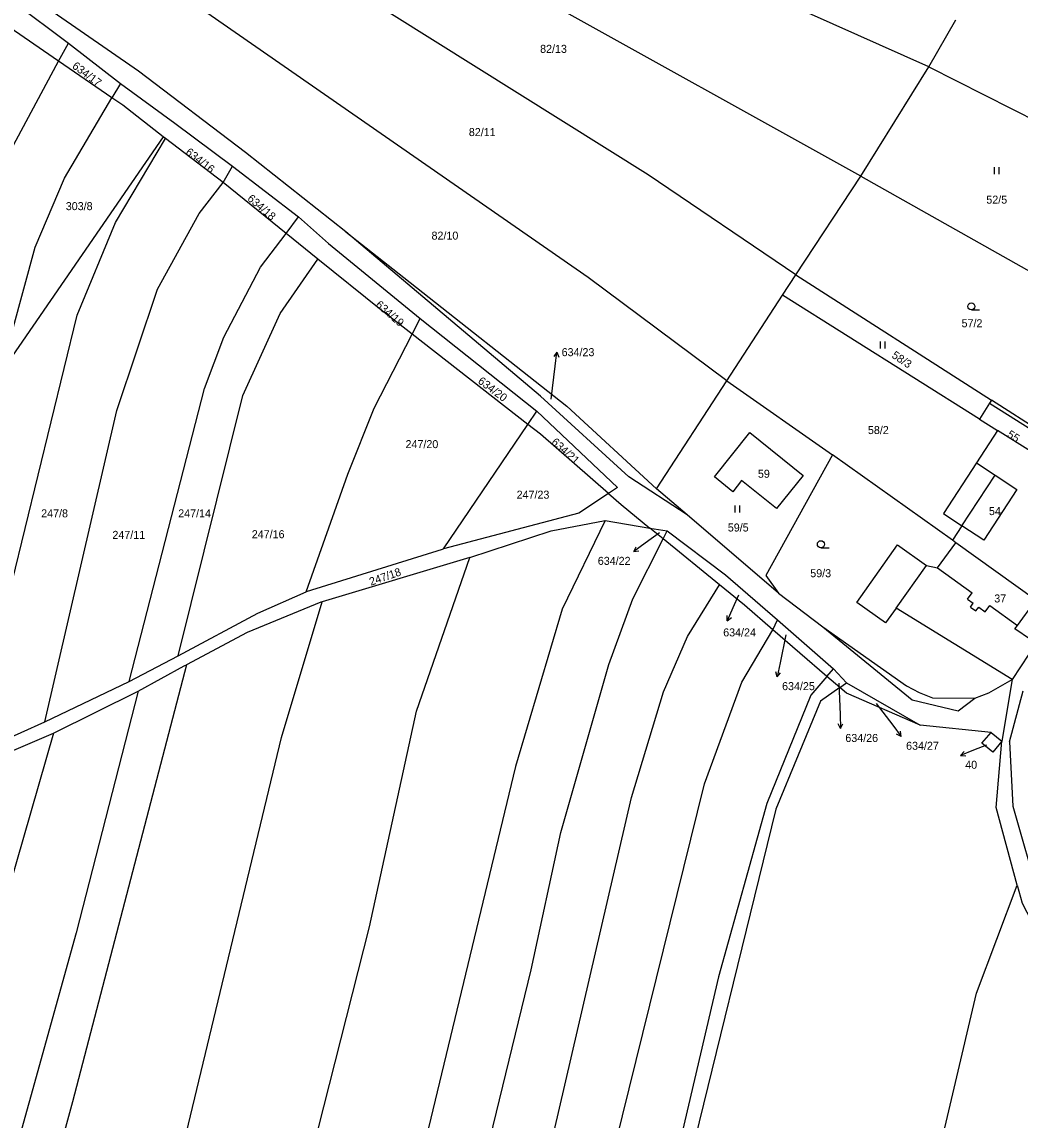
# Model space of a CAD drawing. Extents: x -744566 to -741843, y -1128407 to -1126744.
# Drawn here: x -743260.5 to -743048.6, y -1127789.3 to -1127556.1 of the extents above; entities that cross this region are included whole.
import ezdxf

# ---------------------------------------------------------------- set-up
doc = ezdxf.new("R2010")
doc.units = 0
for name, color, linetype in [('Hranice parcel', 7, 'Continuous'), ('Parcelní čísla', 7, 'Continuous'), ('Pop  PČ popisy', 7, 'Continuous'), ('Vnitřní kresba', 7, 'Continuous'), ('Značky kultur', 7, 'Continuous')]:
    doc.layers.add(name, color=color, linetype=linetype)

msp = doc.modelspace()

# ---------------------------------------------------------------- linework, layer by layer
at = {"layer": 'Hranice parcel'}
for p, q in [((-743082.43, -1127588.87), (-743239.89, -1127501.37)), ((-743067.95, -1127565.66), (-743062.27, -1127555.66)), ((-743252.73, -1127564.48), (-743264.18, -1127556.62)), ((-743252.73, -1127564.48), (-743250.66, -1127560.62)), ((-743250.66, -1127560.62), (-743239.62, -1127569.19)), ((-743241.42, -1127572.24), (-743252.73, -1127564.48)), ((-743082.43, -1127588.87), (-743067.95, -1127565.66)), ((-743067.95, -1127565.66), (-743044.5, -1127577.53)), ((-743239.62, -1127569.19), (-743241.42, -1127572.24)), ((-743230.52, -1127580.51), (-743264.95, -1127630.5)), ((-743230.04, -1127580.88), (-743230.52, -1127580.51)), ((-743217.78, -1127590.26), (-743230.04, -1127580.88)), ((-743217.78, -1127590.26), (-743215.78, -1127586.74)), ((-743215.78, -1127586.74), (-743201.77, -1127597.55)), ((-743204.41, -1127601.05), (-743217.78, -1127590.26)), ((-743096.19, -1127609.82), (-743082.43, -1127588.87)), ((-743082.43, -1127588.87), (-743043.08, -1127611.1)), ((-743204.41, -1127601.05), (-743201.77, -1127597.55)), ((-743197.68, -1127606.48), (-743204.41, -1127601.05)), ((-743099.02, -1127614.17), (-743096.19, -1127609.82)), ((-743096.19, -1127609.82), (-743054.68, -1127636.42)), ((-743110.84, -1127632.34), (-743099.02, -1127614.17)), ((-743057.24, -1127640.46), (-743099.02, -1127614.17)), ((-743177.68, -1127622.43), (-743175.98, -1127619.13)), ((-743175.98, -1127619.13), (-743151.19, -1127638.77)), ((-743153.1, -1127641.6), (-743177.68, -1127622.43)), ((-743125.82, -1127655.26), (-743110.84, -1127632.34)), ((-743110.84, -1127632.34), (-743088.43, -1127648.09)), ((-743043.83, -1127643.37), (-743054.68, -1127636.42)), ((-743153.1, -1127641.6), (-743151.19, -1127638.77)), ((-743170.99, -1127668.05), (-743153.1, -1127641.6)), ((-743057.24, -1127640.46), (-743053.43, -1127642.86)), ((-743053.43, -1127642.86), (-743057.84, -1127649.75)), ((-743046.41, -1127647.29), (-743053.43, -1127642.86)), ((-743062.98, -1127666.21), (-743088.43, -1127648.09)), ((-743119.31, -1127660.83), (-743125.82, -1127655.26)), ((-743136.68, -1127662.01), (-743127.19, -1127663.61)), ((-743099.92, -1127677.43), (-743119.31, -1127660.83)), ((-743060.97, -1127663.13), (-743062.98, -1127666.21)), ((-743124.37, -1127665.91), (-743127.19, -1127663.61)), ((-743127.19, -1127663.61), (-743123.51, -1127664.23)), ((-743124.37, -1127665.91), (-743123.51, -1127664.23)), ((-743112.44, -1127675.65), (-743124.37, -1127665.91)), ((-743062.24, -1127666.73), (-743062.98, -1127666.21)), ((-743045.29, -1127678.95), (-743062.24, -1127666.73)), ((-743165.44, -1127669.87), (-743196.8, -1127679.29)), ((-743099.92, -1127677.43), (-743090.48, -1127684.56)), ((-743101.11, -1127685.19), (-743100.14, -1127683.11)), ((-743100.14, -1127683.11), (-743088.2, -1127693.47)), ((-743089.62, -1127695.12), (-743101.11, -1127685.19)), ((-743044.97, -1127687.73), (-743050.26, -1127695.79)), ((-743237.76, -1127696.22), (-743227.38, -1127690.77)), ((-743089.62, -1127695.12), (-743088.2, -1127693.47)), ((-743086.91, -1127697.47), (-743089.62, -1127695.12)), ((-743088.2, -1127693.47), (-743085.48, -1127696.45)), ((-743255.66, -1127704.74), (-743237.76, -1127696.22)), ((-743086.91, -1127697.47), (-743085.48, -1127696.45)), ((-743085.48, -1127696.45), (-743069.79, -1127705.5)), ((-743050.26, -1127695.79), (-743052.52, -1127708.86)), ((-743253.81, -1127707.15), (-743235.82, -1127698.28)), ((-743270.64, -1127711.51), (-743255.66, -1127704.74)), ((-743268.66, -1127713.55), (-743253.81, -1127707.15)), ((-743054.75, -1127707.06), (-743069.79, -1127705.5)), ((-743054.75, -1127707.06), (-743052.52, -1127708.86))]:
    msp.add_line(p, q, dxfattribs=at)
for points in [[(-743067.95, -1127565.66), (-743113.85, -1127545.15), (-743233.06, -1127485.07)], [(-743096.19, -1127609.82), (-743127.6, -1127588.59), (-743246.36, -1127514.17)], [(-743314.71, -1127527.98), (-743288.02, -1127539.72), (-743267.92, -1127547.88), (-743262.15, -1127552), (-743250.66, -1127560.62)], [(-743110.84, -1127632.34), (-743140.32, -1127610.37), (-743254.82, -1127530.84)], [(-743191.76, -1127600.69), (-743213.04, -1127583.89), (-743235.8, -1127566.59), (-743259.6, -1127550), (-743265.25, -1127546.83)], [(-743282.86, -1127654.54), (-743277.65, -1127629.53), (-743268.85, -1127597.04), (-743263.84, -1127585.18), (-743252.73, -1127564.48)], [(-743239.62, -1127569.19), (-743228.08, -1127577.6), (-743215.78, -1127586.74)], [(-743264.95, -1127630.5), (-743257.74, -1127603.98), (-743251.48, -1127589.3), (-743241.42, -1127572.24)], [(-743230.52, -1127580.51), (-743239.1, -1127573.83), (-743241.42, -1127572.24)], [(-743270.64, -1127711.51), (-743265.43, -1127686.37), (-743248.78, -1127618.41), (-743240.66, -1127598.71), (-743230.04, -1127580.88)], [(-743255.66, -1127704.74), (-743240.36, -1127638.68), (-743231.77, -1127612.89), (-743222.92, -1127596.81), (-743217.78, -1127590.26)], [(-743201.77, -1127597.55), (-743195.41, -1127603.21), (-743175.98, -1127619.13)], [(-743237.76, -1127696.22), (-743221.74, -1127634), (-743217.66, -1127623.08), (-743209.85, -1127608.23), (-743204.41, -1127601.05)], [(-743119.31, -1127660.83), (-743131.7, -1127652.73), (-743150.41, -1127635.6), (-743191.76, -1127600.69)], [(-743191.76, -1127600.69), (-743179.42, -1127610.43), (-743144.82, -1127637.7), (-743125.82, -1127655.26)], [(-743227.38, -1127690.77), (-743213.64, -1127635.49), (-743205.71, -1127618.08), (-743197.68, -1127606.48)], [(-743177.68, -1127622.43), (-743184.29, -1127617.28), (-743197.68, -1127606.48)], [(-743200.21, -1127677.12), (-743191.34, -1127652.2), (-743185.76, -1127638.12), (-743177.68, -1127622.43)], [(-743054.68, -1127636.42), (-743055.09, -1127637.08), (-743057.24, -1127640.46)], [(-743151.19, -1127638.77), (-743134.07, -1127654.97), (-743136.01, -1127656.26)], [(-743136.01, -1127656.26), (-743150.46, -1127643.66), (-743153.1, -1127641.6)], [(-743094.66, -1127652.45), (-743100.33, -1127659.49), (-743107.72, -1127653.53), (-743109.62, -1127655.89), (-743113.52, -1127652.75), (-743105.97, -1127643.33), (-743094.66, -1127652.45)], [(-743088.43, -1127648.09), (-743102.6, -1127673.7), (-743099.92, -1127677.43)], [(-743057.84, -1127649.75), (-743064.89, -1127660.55), (-743060.97, -1127663.13)], [(-743057.84, -1127649.75), (-743053.93, -1127652.35), (-743049.27, -1127655.45), (-743056.31, -1127666.21), (-743060.97, -1127663.13)], [(-743136.01, -1127656.26), (-743142.28, -1127660.44), (-743170.99, -1127668.05)], [(-743136.01, -1127656.26), (-743133.32, -1127658.6), (-743127.19, -1127663.61)], [(-743136.68, -1127662.01), (-743145.81, -1127680.82), (-743155.72, -1127714.23), (-743186.13, -1127840.64), (-743218.63, -1127971.66), (-743232.97, -1128020.31)], [(-743165.44, -1127669.87), (-743148.15, -1127664.23), (-743136.68, -1127662.01)], [(-743123.51, -1127664.23), (-743111.14, -1127673.56), (-743100.14, -1127683.11)], [(-743211.94, -1127995.24), (-743177.21, -1127859.16), (-743152.4, -1127757.44), (-743146.1, -1127728.25), (-743135.93, -1127692.62), (-743130.84, -1127678.65), (-743124.37, -1127665.91)], [(-743050.26, -1127695.79), (-743074.95, -1127680.59), (-743077.21, -1127683.74), (-743083.3, -1127679.41), (-743074.6, -1127667.14), (-743068.46, -1127671.55), (-743066.13, -1127672.07), (-743062.24, -1127666.73)], [(-743237.87, -1127943.87), (-743228.87, -1127911.59), (-743204.89, -1127820), (-743186.75, -1127748.28), (-743176.72, -1127702.48), (-743165.44, -1127669.87)], [(-743170.99, -1127668.05), (-743171.32, -1127668.14), (-743200.21, -1127677.12)], [(-743227.38, -1127690.77), (-743210.43, -1127681.71), (-743200.21, -1127677.12)], [(-743183.31, -1127943.86), (-743166.85, -1127875.07), (-743131.1, -1127720.81), (-743124.32, -1127698.36), (-743119.23, -1127686.62), (-743112.44, -1127675.65)], [(-743101.11, -1127685.19), (-743107.14, -1127679.98), (-743112.44, -1127675.65)], [(-743264.74, -1127937.21), (-743244.37, -1127860.25), (-743227.42, -1127799.64), (-743205.44, -1127708.1), (-743196.8, -1127679.29)], [(-743196.8, -1127679.29), (-743197.04, -1127679.36), (-743212.68, -1127685.82), (-743225.59, -1127692.63)], [(-743044.97, -1127687.73), (-743045.79, -1127687.59), (-743046.39, -1127687.31), (-743049.72, -1127685.03), (-743049.19, -1127684.3), (-743045.58, -1127679.36), (-743045.29, -1127678.95)], [(-743159.84, -1127901.41), (-743140.31, -1127817.95), (-743115.61, -1127717.91), (-743107.65, -1127696.37), (-743101.11, -1127685.19)], [(-743090.48, -1127684.56), (-743071.53, -1127700.11), (-743061.74, -1127702.4), (-743058.22, -1127699.76)], [(-743225.59, -1127692.63), (-743249.75, -1127785.46), (-743287.33, -1127923.2), (-743297.04, -1127954.42)], [(-743235.82, -1127698.28), (-743226.1, -1127692.9), (-743225.59, -1127692.63)], [(-743089.62, -1127695.12), (-743093.02, -1127699.07), (-743102.39, -1127722.13), (-743112.61, -1127758.91), (-743139.42, -1127873.34), (-743159.84, -1127901.41)], [(-743086.91, -1127697.47), (-743090.95, -1127700.36), (-743100.45, -1127723.29), (-743120.32, -1127804.45), (-743137.57, -1127875.6)], [(-743069.79, -1127705.5), (-743085.49, -1127698.7), (-743086.91, -1127697.47)], [(-743058.22, -1127699.76), (-743055.21, -1127698.61), (-743050.26, -1127695.79)], [(-743235.82, -1127698.28), (-743249, -1127749.54), (-743300.05, -1127932.95), (-743303.92, -1127943.26)], [(-743253.81, -1127707.15), (-743266.62, -1127751.47), (-743299.27, -1127867.01), (-743314.24, -1127914.43)], [(-743052.52, -1127708.86), (-743054.42, -1127711.2), (-743056.75, -1127709.3), (-743054.75, -1127707.06)], [(-743049.21, -1127739.41), (-743053.72, -1127722.94), (-743052.52, -1127708.86)], [(-743134.48, -1128101.6), (-743116.84, -1128032.47), (-743112.87, -1128006.6), (-743093.99, -1127930.3), (-743081.3, -1127862.06), (-743057.88, -1127762.39), (-743049.21, -1127739.41)], [(-743049.21, -1127739.41), (-743048.14, -1127743.3), (-743040.35, -1127758.3), (-743030.5, -1127771.33), (-743025.38, -1127776.65)]]:
    msp.add_lwpolyline(points, dxfattribs=at)
at = {"layer": 'Pop  PČ popisy'}
for p, q in [((-743146.944, -1127626.261), (-743147.563, -1127627.194)), ((-743147.31, -1127629.24), (-743146.944, -1127626.261)), ((-743146.944, -1127626.261), (-743146.569, -1127627.316)), ((-743148.16, -1127636.21), (-743147.31, -1127629.24)), ((-743125.15, -1127664.66), (-743128.21, -1127666.85)), ((-743128.21, -1127666.85), (-743130.638, -1127668.614)), ((-743130.638, -1127668.614), (-743130.122, -1127667.62)), ((-743130.638, -1127668.614), (-743129.533, -1127668.43)), ((-743108.42, -1127677.83), (-743109.59, -1127680.57)), ((-743109.59, -1127680.57), (-743110.763, -1127683.332)), ((-743110.763, -1127683.332), (-743110.832, -1127682.215)), ((-743110.763, -1127683.332), (-743109.91, -1127682.606)), ((-743098.31, -1127686.3), (-743099.54, -1127692.26)), ((-743099.54, -1127692.26), (-743100.164, -1127695.195)), ((-743100.164, -1127695.195), (-743100.446, -1127694.112)), ((-743100.164, -1127695.195), (-743099.466, -1127694.32)), ((-743087.06, -1127696.52), (-743086.82, -1127703.2)), ((-743079.13, -1127700.88), (-743075.63, -1127705.47)), ((-743086.82, -1127703.2), (-743086.715, -1127706.199)), ((-743086.715, -1127706.199), (-743087.251, -1127705.216)), ((-743086.715, -1127706.199), (-743086.25, -1127705.181)), ((-743075.63, -1127705.47), (-743073.824, -1127707.867)), ((-743073.824, -1127707.867), (-743074.827, -1127707.368)), ((-743073.824, -1127707.867), (-743074.027, -1127706.766)), ((-743055.74, -1127709.69), (-743058.47, -1127710.78)), ((-743058.47, -1127710.78), (-743061.252, -1127711.904)), ((-743061.252, -1127711.904), (-743060.512, -1127711.065)), ((-743061.252, -1127711.904), (-743060.136, -1127711.993))]:
    msp.add_line(p, q, dxfattribs=at)
at = {"layer": 'Vnitřní kresba'}
for p, q in [((-743055.09, -1127637.08), (-743044.24, -1127643.99)), ((-743060.97, -1127663.13), (-743053.93, -1127652.35)), ((-743074.95, -1127680.59), (-743068.46, -1127671.55)), ((-743066.13, -1127672.07), (-743058.8, -1127677.37)), ((-743059.75, -1127678.69), (-743058.8, -1127677.37)), ((-743059.75, -1127678.69), (-743058.57, -1127679.56)), ((-743059.15, -1127680.38), (-743058.57, -1127679.56)), ((-743059.15, -1127680.38), (-743057.98, -1127681.22)), ((-743057.98, -1127681.22), (-743057.39, -1127680.41)), ((-743057.39, -1127680.41), (-743056.02, -1127681.41)), ((-743056.02, -1127681.41), (-743055.05, -1127680.07)), ((-743055.05, -1127680.07), (-743049.19, -1127684.3)), ((-743090.48, -1127684.56), (-743072.72, -1127697.13)), ((-743072.72, -1127697.13), (-743070.01, -1127698.54)), ((-743070.01, -1127698.54), (-743067.17, -1127699.66)), ((-743067.17, -1127699.66), (-743058.22, -1127699.76)), ((-743050.88, -1127709.04), (-743047.98, -1127698.19)), ((-743050.88, -1127709.04), (-743050.12, -1127722.67)), ((-743050.12, -1127722.67), (-743044.56, -1127742.19))]:
    msp.add_line(p, q, dxfattribs=at)
at = {"layer": 'Značky kultur'}
for p, q in [((-743054.051, -1127588.47), (-743054.051, -1127586.97)), ((-743053.05, -1127588.47), (-743053.05, -1127586.97)), ((-743058.953, -1127617.29), (-743057.203, -1127617.29)), ((-743078.241, -1127625.49), (-743078.241, -1127623.99)), ((-743077.24, -1127625.49), (-743077.24, -1127623.99)), ((-743109.081, -1127660.33), (-743109.081, -1127658.83)), ((-743108.08, -1127660.33), (-743108.08, -1127658.83)), ((-743090.903, -1127667.8), (-743089.153, -1127667.8))]:
    msp.add_line(p, q, dxfattribs=at)
for centre in [(-743058.953, -1127616.54), (-743090.903, -1127667.05)]:
    msp.add_circle(centre, 0.75, dxfattribs=at)

# ---------------------------------------------------------------- texts
at = {"layer": 'Parcelní čísla'}
for s, p in [('82/13', (-743150.51, -1127562.7)), ('82/11', (-743165.64, -1127580.37)), ('52/5', (-743055.781, -1127594.72)), ('303/8', (-743251.21, -1127596.1)), ('82/10', (-743173.56, -1127602.36)), ('57/2', (-743061.031, -1127620.97)), ('634/23', (-743145.94, -1127627.11)), ('58/2', (-743080.911, -1127643.65)), ('247/20', (-743179.08, -1127646.64)), ('59', (-743104.27, -1127652.93)), ('247/23', (-743155.5, -1127657.37)), ('247/8', (-743256.43, -1127661.34)), ('247/14', (-743227.34, -1127661.34)), ('54', (-743055.22, -1127660.86)), ('59/5', (-743110.661, -1127664.34)), ('247/11', (-743241.31, -1127665.91)), ('247/16', (-743211.72, -1127665.77)), ('634/22', (-743138.261, -1127671.423)), ('59/3', (-743093.151, -1127674.05)), ('37', (-743054.092, -1127679.41)), ('634/24', (-743111.64, -1127686.62)), ('634/25', (-743099.14, -1127698.033)), ('634/26', (-743085.71, -1127709.033)), ('634/27', (-743072.81, -1127710.693)), ('40', (-743060.26, -1127714.723))]:
    msp.add_text(s, height=1.7, dxfattribs=at).set_placement(p)
for s, rotation, p in [('634/17', 323, (-743249.991, -1127565.798)), ('634/16', 322, (-743225.923, -1127584.069)), ('634/18', 319, (-743212.797, -1127593.851)), ('634/19', 319, (-743185.567, -1127616.401)), ('58/3', 326, (-743076.013, -1127627.291)), ('634/20', 323, (-743163.861, -1127632.698)), ('55', 328, (-743051.52, -1127644.15)), ('634/21', 318, (-743148.248, -1127645.561)), ('247/18', 19, (-743186.433, -1127675.863))]:
    msp.add_text(s, height=1.7, rotation=rotation, dxfattribs=at).set_placement(p)

doc.saveas('drawing.dxf')
